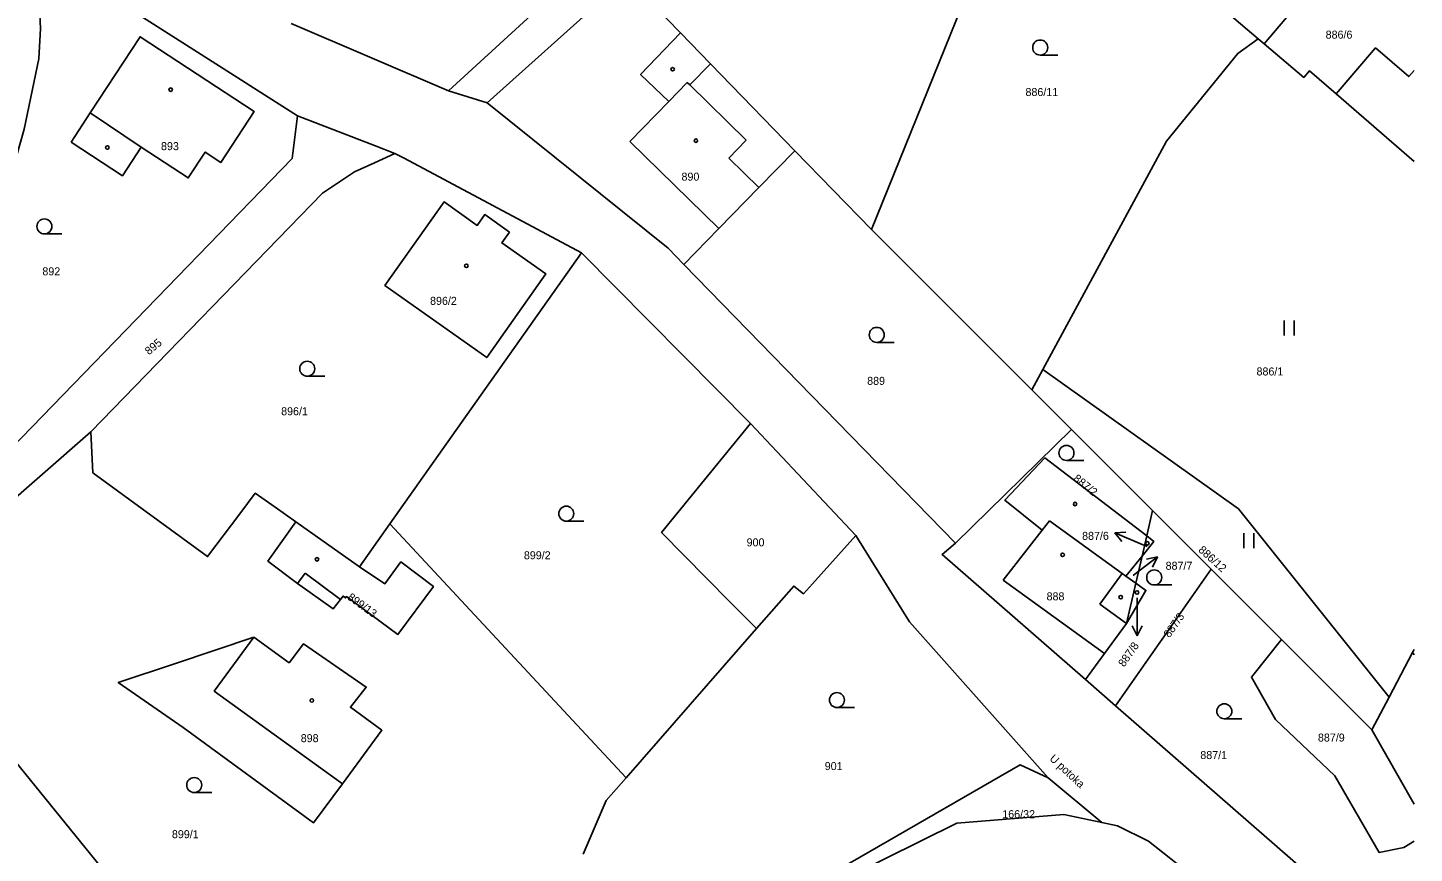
# Model space of a CAD drawing. Extents: x -719706 to -718922, y -950351 to -949651.
# Drawn here: x -719060.8 to -718922.2, y -949956 to -949873.5 of the extents above; entities that cross this region are included whole.
import ezdxf

# ---------------------------------------------------------------- set-up
doc = ezdxf.new("R2010")
doc.units = 0
doc.layers.add('Doplňující texty', color=7, linetype='Continuous')

msp = doc.modelspace()

# ---------------------------------------------------------------- linework, layer by layer
at = {"layer": 'Doplňující texty'}
for p, q in [((-719018.77, -949879.79), (-719003.64, -949865.91)), ((-719014.89, -949880.97), (-719000.95, -949868.45)), ((-719034.51, -949873.05), (-719018.77, -949879.79)), ((-718937.22, -949875.09), (-718937.82, -949874.58)), ((-718994.63, -949879.19), (-718992.56, -949877.08)), ((-718959.61, -949876.2), (-718957.86, -949876.2)), ((-719018.77, -949879.79), (-719014.89, -949880.97)), ((-718996.75, -949880.84), (-718994.89, -949878.94)), ((-718994.89, -949878.94), (-718994.63, -949879.19)), ((-718994.63, -949879.19), (-718989, -949884.71)), ((-718996.75, -949880.84), (-719000.65, -949884.83)), ((-719054.6, -949881.98), (-719049.49, -949885.4)), ((-718991.74, -949893.55), (-719000.65, -949884.83)), ((-718989, -949884.71), (-718990.75, -949886.5)), ((-718990.75, -949886.5), (-718987.73, -949889.45)), ((-718984.13, -949885.77), (-718976.47, -949893.65)), ((-718960.44, -949909.68), (-718976.47, -949893.65)), ((-719059.17, -949894.09), (-719057.42, -949894.09)), ((-719024.64, -949923.09), (-719005.48, -949895.99)), ((-718988.58, -949913.04), (-719005.48, -949895.99)), ((-718935.23, -949904.26), (-718935.23, -949902.76)), ((-718934.23, -949904.26), (-718934.23, -949902.76)), ((-718975.95, -949904.93), (-718974.2, -949904.93)), ((-719032.89, -949908.32), (-719031.14, -949908.32)), ((-718960.44, -949909.68), (-718959.33, -949907.64)), ((-718956.49, -949913.63), (-718960.44, -949909.68)), ((-718978.05, -949924.26), (-718988.58, -949913.04)), ((-719068.92, -949926.48), (-719054.53, -949913.89)), ((-718956.49, -949913.63), (-718968.09, -949925.01)), ((-718948.37, -949921.74), (-718956.49, -949913.63)), ((-718956.98, -949916.74), (-718955.23, -949916.74)), ((-719006.99, -949922.81), (-719005.24, -949922.81)), ((-718959.4, -949923.72), (-718958.67, -949922.79)), ((-718958.67, -949922.79), (-718951.4, -949928.05)), ((-718948.96, -949924.29), (-718948.37, -949921.74)), ((-718942.5, -949927.61), (-718948.37, -949921.74)), ((-719034.03, -949922.88), (-719027.67, -949927.37)), ((-719027.67, -949927.37), (-719024.64, -949923.09)), ((-719001.02, -949948.46), (-719024.64, -949923.09)), ((-718952.16, -949923.98), (-718951.05, -949923.91)), ((-718949.4, -949925.15), (-718952.16, -949923.98)), ((-718952.16, -949923.98), (-718951.44, -949924.83)), ((-718939.24, -949925.52), (-718939.24, -949924.02)), ((-718938.24, -949925.52), (-718938.24, -949924.02)), ((-718949.43, -949926.3), (-718948.96, -949924.29)), ((-718948.93, -949925.36), (-718949.4, -949925.15)), ((-718950.28, -949928.2), (-718947.88, -949926.39)), ((-718949.43, -949926.3), (-718950.06, -949929)), ((-718947.88, -949926.39), (-718948.98, -949926.6)), ((-718947.88, -949926.39), (-718948.38, -949927.4)), ((-719033.87, -949929.03), (-719033.1, -949928.02)), ((-719033.1, -949928.02), (-719029.56, -949930.65)), ((-718951.4, -949928.05), (-718953.63, -949931.11)), ((-718942.5, -949927.61), (-718952.09, -949941.26)), ((-718951.4, -949928.05), (-718951.04, -949928.3)), ((-718950.3, -949928.22), (-718950.28, -949928.2)), ((-718935.48, -949934.63), (-718942.5, -949927.61)), ((-718953.19, -949936.06), (-718963.3, -949928.72)), ((-718950.99, -949933.03), (-718950.06, -949929)), ((-718948.21, -949929.19), (-718946.46, -949929.19)), ((-718953.63, -949931.11), (-718950.99, -949933.03)), ((-718949.92, -949930.48), (-718949.92, -949931.28)), ((-718949.92, -949931.28), (-718949.92, -949934.28)), ((-718987.98, -949933.56), (-719001.02, -949948.46)), ((-718950.99, -949933.03), (-718953.19, -949936.06)), ((-718949.92, -949934.28), (-718950.42, -949933.28)), ((-718949.92, -949934.28), (-718949.42, -949933.28)), ((-719042.2, -949939.82), (-719038.23, -949934.42)), ((-718935.48, -949934.63), (-718926.45, -949943.66)), ((-718955.08, -949938.66), (-718953.19, -949936.06)), ((-718924.73, -949940.41), (-718922.37, -949935.96)), ((-718922.37, -949935.96), (-718922.21, -949935.66)), ((-718922.21, -949936.18), (-718922.37, -949935.96)), ((-718955.08, -949938.66), (-718952.09, -949941.26)), ((-719029.36, -949949.07), (-719042.2, -949939.82)), ((-718926.45, -949943.66), (-718924.73, -949940.41)), ((-718979.93, -949941.45), (-718978.18, -949941.45)), ((-718941.2, -949942.57), (-718939.45, -949942.57)), ((-718926.45, -949943.66), (-718922.21, -949951.11)), ((-718953.43, -949952.95), (-718958.8, -949948.46)), ((-719044.19, -949949.95), (-719042.44, -949949.95))]:
    msp.add_line(p, q, dxfattribs=at)
for points in [[(-718976.47, -949893.65), (-718960.12, -949853.18), (-718952.74, -949836.01)], [(-719033.87, -949882.27), (-719054.24, -949869.28), (-719063.9, -949853.6)], [(-718937.22, -949875.09), (-718936.66, -949874.42), (-718929.73, -949866.21), (-718928.11, -949864.29)], [(-719060.91, -949866.11), (-719060.26, -949868.21), (-719059.66, -949871.49), (-719059.57, -949873.53), (-719059.71, -949876.58), (-719061.19, -949883.61), (-719061.93, -949886.22), (-719062.78, -949888.55), (-719063.94, -949890.99), (-719065.34, -949893.32), (-719069.95, -949899.51), (-719072.25, -949902.55), (-719073.6, -949904.5), (-719074.92, -949906.95), (-719075.6, -949908.76), (-719075.7, -949910.05)], [(-719000.95, -949868.45), (-718995.57, -949873.98), (-718992.56, -949877.08), (-718984.13, -949885.77)], [(-718943.44, -949868.63), (-718940.78, -949870.93), (-718941.35, -949871.59), (-718937.82, -949874.58)], [(-718995.57, -949873.98), (-718999.57, -949878.13), (-718996.75, -949880.84)], [(-719056.5, -949884.9), (-719054.6, -949881.98), (-719049.6, -949874.37), (-719038.18, -949881.85), (-719041.52, -949886.94), (-719043.09, -949885.91), (-719044.78, -949888.49), (-719049.49, -949885.4), (-719051.36, -949888.27), (-719056.5, -949884.9)], [(-718937.82, -949874.58), (-718939.85, -949876.03), (-718946.97, -949884.82), (-718959.33, -949907.64)], [(-718930.03, -949880.08), (-718932.69, -949877.78), (-718933.26, -949878.44), (-718937.22, -949875.09)], [(-718922.21, -949877.73), (-718922.76, -949878.35), (-718926.07, -949875.49), (-718930.03, -949880.08)], [(-719014.89, -949880.97), (-718996.82, -949895.51), (-718995.24, -949897.13)], [(-718922.21, -949886.86), (-718930.03, -949880.08)], [(-719065.67, -949918.79), (-719034.39, -949886.53), (-719033.87, -949882.27)], [(-719024.13, -949886.03), (-719026.15, -949885.25), (-719033.87, -949882.27)], [(-719054.53, -949913.89), (-719031.36, -949890.02), (-719028.15, -949887.89), (-719026.18, -949886.98), (-719024.13, -949886.03)], [(-719005.48, -949895.99), (-719023.2, -949886.52), (-719024.13, -949886.03)], [(-718984.13, -949885.77), (-718987.73, -949889.45), (-718991.74, -949893.55), (-718995.24, -949897.13)], [(-719012.66, -949893.91), (-719013.42, -949894.99), (-719009.03, -949898.09), (-719014.95, -949906.45), (-719025.12, -949899.24), (-719019.21, -949890.89), (-719015.9, -949893.23), (-719015.14, -949892.15), (-719012.66, -949893.91)], [(-718995.24, -949897.13), (-718982.46, -949910.26), (-718968.09, -949925.01)], [(-718959.33, -949907.64), (-718939.77, -949921.59), (-718924.73, -949940.41)], [(-718988.58, -949913.04), (-718997.46, -949923.94), (-718990.67, -949930.83), (-718987.98, -949933.56)], [(-719054.53, -949913.89), (-719054.31, -949917.97), (-719042.86, -949926.36), (-719039.63, -949922.08), (-719038.08, -949920.02), (-719036.1, -949921.42), (-719034.03, -949922.88)], [(-718963.3, -949928.72), (-718959.4, -949923.72), (-718963.16, -949920.71), (-718959.13, -949916.48), (-718948.96, -949924.29)], [(-719027.67, -949927.37), (-719025.12, -949929.07), (-719023.52, -949926.88), (-719020.27, -949929.35), (-719023.82, -949934.14), (-719028.97, -949930.36), (-719029.06, -949930.49), (-719029.31, -949930.31), (-719029.56, -949930.65), (-719030.29, -949931.57), (-719033.87, -949929.03), (-719036.82, -949926.81), (-719034.03, -949922.88)], [(-718987.98, -949933.56), (-718984.25, -949929.3), (-718983.27, -949930.07), (-718982.38, -949929.08), (-718978.05, -949924.26)], [(-718958.8, -949948.46), (-718972.67, -949932.89), (-718978.05, -949924.26)], [(-718968.09, -949925.01), (-718969.42, -949926.15), (-718955.08, -949938.66)], [(-718948.96, -949924.29), (-718948.25, -949924.83), (-718949.43, -949926.3)], [(-719036.99, -949977.77), (-719062.57, -949946.23), (-719068.83, -949926.75), (-719068.92, -949926.48)], [(-718950.06, -949929), (-718951.04, -949928.3), (-718949.43, -949926.3)], [(-718950.06, -949929), (-718949.04, -949929.73), (-718950.99, -949933.03)], [(-719038.23, -949934.42), (-719046.07, -949937.03), (-719051.79, -949938.93), (-719045.31, -949943.44), (-719032.28, -949952.99), (-719029.36, -949949.07), (-719025.42, -949943.71), (-719028.57, -949941.42), (-719026.99, -949939.4), (-719033.26, -949935.07), (-719034.71, -949936.97), (-719038.23, -949934.42)], [(-718922.21, -949954.81), (-718923.24, -949955.44), (-718925.73, -949955.94), (-718930.16, -949948.27), (-718936.09, -949942.64), (-718938.49, -949938.4), (-718935.48, -949934.63)], [(-718952.09, -949941.26), (-718922.62, -949966.96), (-718922.21, -949967.74)], [(-718991.66, -949964.5), (-718961.61, -949947.19), (-718958.8, -949948.46)], [(-719001.02, -949948.46), (-719003.01, -949950.73), (-719005.31, -949956.1)], [(-718953.43, -949952.95), (-718957.26, -949952.13), (-718967.95, -949953), (-718978.76, -949958.38), (-718990.78, -949967.16), (-718995.18, -949975.95), (-718998.39, -949983.61), (-719002.55, -949990.4), (-719005.48, -949993.43), (-719008.54, -949995.43), (-719011.46, -949996.58), (-719015.26, -949997.06), (-719020.18, -949996.83), (-719024.2, -949995.68), (-719026.6, -949994.41), (-719029.53, -949992.2)], [(-718934.66, -949968.65), (-718935.31, -949967.58), (-718938.34, -949963.88), (-718945.93, -949957.06), (-718948.78, -949954.8), (-718951.87, -949953.29), (-718953.43, -949952.95)]]:
    msp.add_lwpolyline(points, dxfattribs=at)
for centre, radius in [((-718959.61, -949875.45), 0.75), ((-718996.36, -949877.62), 0.175), ((-719046.54, -949879.66), 0.175), ((-719052.87, -949885.45), 0.175), ((-718994.03, -949884.77), 0.175), ((-719059.17, -949893.34), 0.75), ((-719016.98, -949897.28), 0.175), ((-718975.95, -949904.18), 0.75), ((-719032.89, -949907.57), 0.75), ((-718956.98, -949915.99), 0.75), ((-719006.99, -949922.06), 0.75), ((-718956.12, -949921.1), 0.175), ((-718948.89, -949925.03), 0.175), ((-719031.92, -949926.62), 0.175), ((-718957.37, -949926.18), 0.175), ((-718948.21, -949928.44), 0.75), ((-718949.93, -949929.95), 0.175), ((-718951.56, -949930.41), 0.175), ((-719032.43, -949940.75), 0.175), ((-718979.93, -949940.7), 0.75), ((-718941.2, -949941.82), 0.75), ((-719044.19, -949949.2), 0.75)]:
    msp.add_circle(centre, radius, dxfattribs=at)

# ---------------------------------------------------------------- texts
for s, p in [('886/6', (-718931.07, -949874.56)), ('886/11', (-718961.08, -949880.3)), ('893', (-719047.51, -949885.71)), ('890', (-718995.47, -949888.76)), ('892', (-719059.37, -949898.23)), ('896/2', (-719020.61, -949901.18)), ('886/1', (-718937.98, -949908.24)), ('889', (-718976.91, -949909.18)), ('896/1', (-719035.5, -949912.22)), ('887/6', (-718955.42, -949924.68)), ('900', (-718988.96, -949925.33)), ('899/2', (-719011.23, -949926.62)), ('887/7', (-718947.07, -949927.67)), ('888', (-718958.97, -949930.73)), ('898', (-719033.54, -949944.91)), ('887/9', (-718931.84, -949944.85)), ('887/1', (-718943.6, -949946.6)), ('901', (-718981.15, -949947.7)), ('166/32', (-718963.4, -949952.51)), ('899/1', (-719046.42, -949954.51))]:
    msp.add_text(s, height=0.8, dxfattribs=at).set_placement(p)
for s, rotation, p in [('895', 40, (-719048.71, -949906.24)), ('887/2', 321, (-718956.37, -949918.67)), ('886/12', 318, (-718943.86, -949925.78)), ('899/13', 324, (-719028.94, -949930.57)), ('887/3', 55, (-718946.68, -949934.53)), ('887/8', 55, (-718951.22, -949937.45)), ('U potoka', 317, (-718958.74, -949946.64))]:
    msp.add_text(s, height=0.8, rotation=rotation, dxfattribs=at).set_placement(p)

doc.saveas('drawing.dxf')
